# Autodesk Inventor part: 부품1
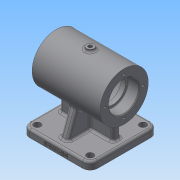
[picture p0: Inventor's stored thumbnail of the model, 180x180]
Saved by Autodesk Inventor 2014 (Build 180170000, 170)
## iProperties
Created: 2019-06
Part Number: 부품1
Material: 일반
Document SubType Name: Modeling
Designer: net
Density: 1 g/cm^3
Appearance: 기본값
Mass: 225.527 g
Surface Area: 626.694 cm^2
Volume: 225.527 cm^3
Author: net
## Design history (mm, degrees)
sketch "스케치1"
  geometry: L1 (45, 0)-(-45, 0); L2 (45, 20)-(30, 20); L3 (30, 20)-(30, 17); L4 (30, 17)-(24, 17); L5 (24, 17)-(24, 25); L6 (24, 25)-(-24, 25); L7 (-24, 25)-(-24, 17); L8 (-24, 17)-(-30, 17); L9 (-30, 17)-(-30, 20); L10 (-30, 20)-(-45, 20); L11 (-45, 20)-(-45, 32); L12 (-45, 32)-(45, 32); L13 (45, 32)-(45, 20); 4 further points
  constraints: 26 end point, 10 parallel, 3 midpoint, 2 vertical alignment, 1 coincident, 1 collinear, 1 horizontal, 1 perpendicular
  dimensions: "d0" = 90 distance of L1.start L1.end; "d1" = 48 distance of L5.end L6.end; "d2" = 15 distance of L2.start L2.end; "d3" = 15 distance of L9.end L10.end; "d4" = 50 diameter of L6 L1; "d5" = 34 diameter of L4 L1; "d6" = 40 diameter of L2 L1; "d7" = 34 diameter of L8 L1; "d8" = 40 diameter of L10 L1; "d9" = 64 diameter of L12 L1; "d10" = 6 distance of L3.end L4.end
revolve "회전1" sketch "스케치1" stored, may be unused: angle "d11" = 90 deg
node "작업 평면1"
sketch "스케치2"
  geometry: L1 (-45, 45)-(45, 45); L2 (45, 45)-(45, -45); L3 (45, -45)-(-45, -45); L4 (-45, -45)-(-45, 45); 3 further points
  constraints: 8 end point, 2 midpoint, 2 parallel, 1 horizontal, 1 horizontal alignment, 1 perpendicular, 1 vertical alignment
  dimensions: "d13" = 90 distance of L2.end L3.end; "d14" = 90 distance of L1.end L2.end
extrude "돌출1" join sketch "스케치2" distance "d15" = 10; taper "d16" = 0 deg
sketch "스케치3"
  geometry: L1 (-45, 45)-(-45, -45) reference; L2 (-35, 5)-(35, 5); L3 (35, 5)-(35, -5); L4 (35, -5)-(-35, -5); L5 (-35, -5)-(-35, 5); 2 further points
  constraints: 8 end point, 2 parallel, 1 horizontal, 1 horizontal alignment, 1 midpoint, 1 perpendicular
  dimensions: "d17" = 70 distance of L3.end L4.end; "d18" = 10 distance of L2.end L3.end; "d19" = 10 distance between parallel lines of L5 L1
extrude "돌출2" join sketch "스케치3" stored distance "d20" = 10; taper "d21" = 0 deg
sketch "스케치4"
  geometry: L1 (45, -55)-(45, -65) reference; L2 (45, -65)-(-45, -65) reference; L3 (-45, -65)-(-45, -55) reference; L4 (-45, -55)-(-5, -55) reference; L5 (-5, -55)-(-5, -31.607) reference; L6 (5, -31.607)-(5, -55) reference; L7 (5, -55)-(45, -55) reference; L8 (-23.058, -22.189)-(-35, -55); C1 r 25 at (0, 0) reference; A1 r 32 centre (0, 0) between (5, -31.607) and (-5, -31.607) reference; 1 further point
  constraints: 2 end point, 1 point on circle, 1 point on line
  dimensions: "d22" = 110 deg angle of L4 L8; "d23" = 10 distance from line of L3 L8.end
feature "리브1" sketch "스케치4" dims "d24" = 1, "d25" = 10, "d26" = 0, "d27" = 0, "d28" = 1, "d29" = 1
fillet "모깎기1" dims "d30" = 10
fillet "모깎기2" dims "d31" = 3
sketch "스케치5"
  geometry: C1 r 4.5 at (-35, 35); C2 r 4.5 at (35, 35); C3 r 4.5 at (-35, -35); C4 r 4.5 at (35, -35); A1 r 7 centre (-35, -35) between (-42, -35) and (-35, -42) reference; A2 r 7 centre (35, -35) between (35, -42) and (42, -35) reference; A3 r 7 centre (35, 35) between (42, 35) and (35, 42) reference; A4 r 7 centre (-35, 35) between (-35, 42) and (-42, 35) reference; 1 further point
  constraints: 4 centre point, 4 coincident
  dimensions: "d32" = 9 diameter of C1; "d33" = 9 diameter of C2; "d34" = 9 diameter of C3; "d35" = 9 diameter of C4
extrude "돌출3" cut sketch "스케치5" stored distance "d36" = 10; taper "d37" = 0 deg
sketch "스케치6" dims "d38" = 50
  geometry: C1 r 20 at (0, 0) reference; 2 further points
  constraints: 2 horizontal alignment, 1 coincident, 2 other
hole "구멍1" sketch "스케치6" at (25, 0) diameter "d39" = 3.242; stored, may be unused: countersink angle "d43" = 90 deg, drill point angle "d45" = 118 deg; dims "d40" = 7, "d41" = 4, "d42" = 2, "d44" = 9
sketch "스케치7" dims "d49" = 50
  geometry: C1 r 20 at (0, 0) reference; 2 further points
  constraints: 2 horizontal alignment, 1 coincident, 2 other
hole "구멍2" sketch "스케치7" at (-25, 0) diameter "d50" = 3.242; stored, may be unused: countersink angle "d54" = 90 deg, drill point angle "d56" = 118 deg; dims "d51" = 7, "d52" = 4, "d53" = 2, "d55" = 9
sketch "스케치8"
  geometry: L1 (-42, -55)-(-35, -55) reference; L2 (-35, -55)-(-23.058, -22.189) reference; L3 (23.058, -22.189)-(35, -55) reference; L4 (35, -55)-(42, -55) reference; L5 (45, -58)-(45, -65) reference; L6 (45, -65)-(-45, -65) reference; L7 (-45, -65)-(-45, -58) reference; L8 (0, 32)-(0, 35); C1 r 25 at (0, 0) reference; A1 r 3 centre (-42, -58) between (-42, -55) and (-45, -58) reference; A2 r 32 centre (0, 0) between (23.058, -22.189) and (-23.058, -22.189) reference; A3 r 3 centre (42, -58) between (45, -58) and (42, -55) reference; 1 further point
  constraints: 2 end point, 1 parallel, 1 point on circle
  dimensions: "d60" = 100 distance from line of L6 L8.end
  node "절단 모서리 투영2"
node "작업 평면2"
sketch "스케치9"
  geometry: C1 r 5 at (0, 0); 1 further point
  constraints: 1 centre point, 1 coincident
  dimensions: "d61" = 10 diameter of C1
extrude "돌출4" join sketch "스케치9" stored distance "d62" = 10; taper "d63" = 0 deg
sketch "스케치10"
  geometry: C1 r 5 at (0, 0) reference; 1 further point
  constraints: 1 coincident
hole "구멍3" sketch "스케치10" at (0, 0) diameter "d64" = 4.917; stored, may be unused: countersink angle "d68" = 90 deg, drill point angle "d70" = 118 deg; dims "d65" = 40, "d66" = 4, "d67" = 2, "d69" = 9
sketch "스케치11"
  geometry: L1 (45, -35)-(45, 35) reference; L2 (-22, 40)-(22, 40); L3 (25, 37)-(25, 35); L4 (35, 25)-(37, 25); L5 (40, 22)-(40, -22); L6 (37, -25)-(35, -25); L7 (25, -35)-(25, -37); L8 (22, -40)-(-22, -40); L9 (-25, -37)-(-25, -35); L10 (-35, -25)-(-37, -25); L11 (-40, -22)-(-40, 22); L12 (-37, 25)-(-35, 25); L13 (-25, 35)-(-25, 37); L14 (0, 40)-(0, -40); L15 (-40, 0)-(40, 0); C1 r 4.5 at (-35, -35) reference; A1 r 10 centre (35, 35) between (45, 35) and (35, 45) reference; A2 r 10 centre (-35, 35) between (-35, 45) and (-45, 35) reference; A3 r 10 centre (-35, 35) between (-35, 25) and (-25, 35); A4 r 10 centre (35, 35) between (25, 35) and (35, 25); A5 r 10 centre (35, -35) between (35, -25) and (25, -35); A6 r 10 centre (-35, -35) between (-25, -35) and (-35, -25); A7 r 3 centre (-22, 37) between (-22, 40) and (-25, 37); A8 r 3 centre (-37, 22) between (-37, 25) and (-40, 22); A9 r 3 centre (-37, -22) between (-40, -22) and (-37, -25); A10 r 3 centre (-22, -37) between (-25, -37) and (-22, -40); A11 r 3 centre (22, -37) between (22, -40) and (25, -37); A12 r 3 centre (37, -22) between (37, -25) and (40, -22); A13 r 3 centre (37, 22) between (40, 22) and (37, 25); A14 r 3 centre (22, 37) between (25, 37) and (22, 40); 2 further points
  constraints: 28 end point, 24 point on circle, 24 tangent, 12 centre point, 10 equal radius, 8 parallel, 6 midpoint, 5 perpendicular, 4 coincident, 2 horizontal alignment, 2 vertical alignment, 1 collinear
  dimensions: "d71" = 80 distance between parallel lines of L5 L11; "d72" = 80 distance between parallel lines of L8 L2; "d73" = 10 radius of A3; "d74" = 3 radius of A7
extrude "돌출5" cut sketch "스케치11" distance "d75" = 5; taper "d76" = 0 deg
sketch "스케치12"
  geometry: L1 (70, 0)-(0, 0) reference; L2 (-10, 7)-(-10, 0) reference; 2 further points
  constraints: 1 other
  dimensions: "d77" = 4 distance from line of L1 point (35, 4); "d78" = 45 distance from line of L2 point (35, 4)
feature "엠보싱1" sketch "스케치12" dims "d13" = 90, "d14" = 90, "d79" = 0.5, "d80" = 0
fillet "모깎기3" dims "d81" = 3
fillet "모깎기4" dims "d82" = 3
chamfer "모따기1" distance "d83" = 1; stored, may be unused: second distance "d84" = 2, angle "d85" = 45 deg
chamfer "모따기2" distance "d86" = 1; stored, may be unused: second distance "d87" = 2, angle "d88" = 45 deg
fillet "모깎기5" dims "d89" = 3
fillet "모깎기6" dims "d90" = 0.6
node "솔리드1"
mirror "대칭1"
pattern_circular "원형 패턴1" dims angle "d47" = 360 deg
pattern_circular "원형 패턴2" dims angle "d58" = 360 deg
node "절단 모서리 투영1"
other parameters: "d12" = -65
